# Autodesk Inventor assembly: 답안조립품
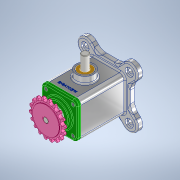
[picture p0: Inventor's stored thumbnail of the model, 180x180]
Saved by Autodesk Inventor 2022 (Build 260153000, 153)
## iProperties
Created: 2022-05
Part Number: 답안조립품
Document SubType Name: Assembly
Designer: Admin
Author: Admin
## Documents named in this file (11)
- C:\Users\Admin\Desktop\720509V1003\답안조립품.iam
- C:\Users\Admin\Desktop\720509V1003\본체.ipt
- C:\Users\Admin\Desktop\720509V1003\커버.ipt
- C:\Users\Admin\Desktop\720509V1003\베어링 6203.ipt
- C:\Users\Admin\Desktop\720509V1003\편심축.ipt
- C:\Users\Admin\Desktop\720509V1003\슬라이더.ipt
- C:\Users\Admin\Desktop\720509V1003\부시.ipt
- C:\Users\Admin\Desktop\720509V1003\오일 실.ipt
- C:\Users\Admin\Desktop\720509V1003\볼트 M4.ipt
- C:\Users\Admin\Desktop\720509V1003\키 4 x 4 x 14.ipt
- C:\Users\Admin\Desktop\720509V1003\스프로킷.ipt
